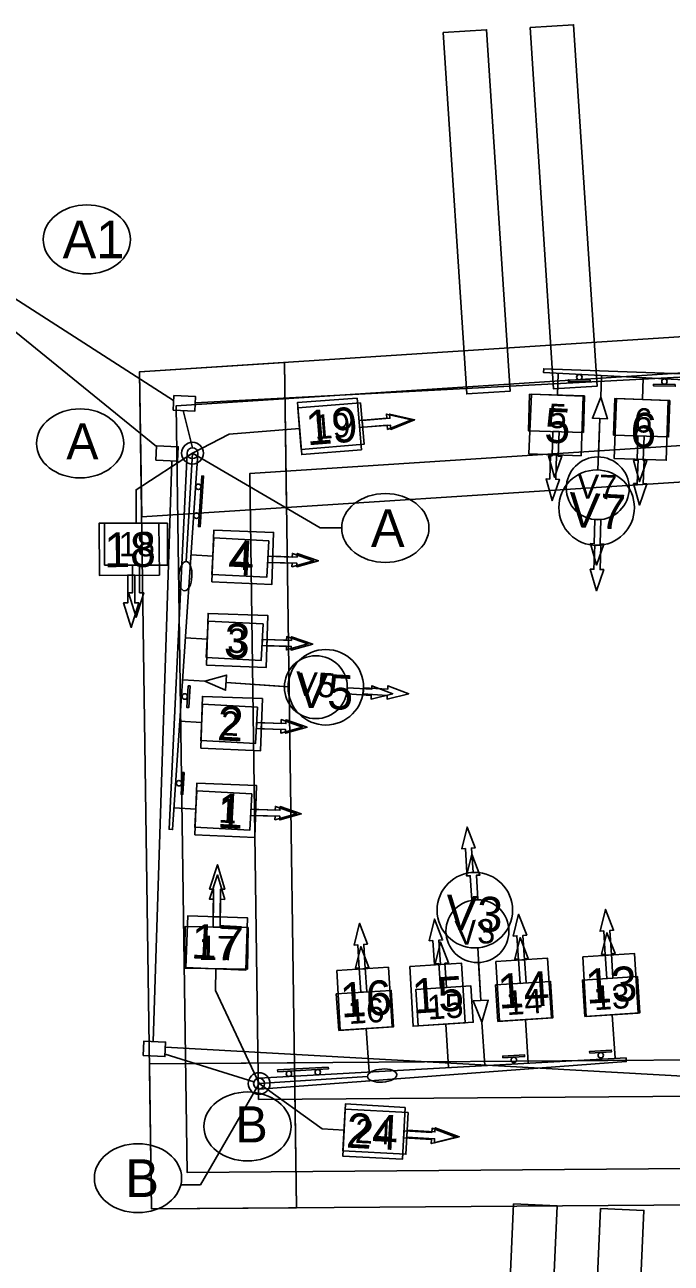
# Model space of a CAD drawing. Extents: x 21 to 686546, y 24 to 735466.
# Drawn here: x 686181.5 to 686270.7, y 734785.5 to 734956.5 of the extents above; entities that cross this region are included whole.
import ezdxf

# ---------------------------------------------------------------- set-up
doc = ezdxf.new("R2010")
doc.units = 0
for name, color, linetype in [('PEDXLIMITS-PR', 7, 'Continuous'), ('signal wiring diagram', 7, 'Continuous'), ('SIGNAL-PLAN VIEW LABLES', 7, 'Continuous'), ('SIGNAL-PR', 7, 'Continuous'), ('signal-pr-conduit', 7, 'Continuous'), ('Video-Zones-pr', 7, 'Continuous')]:
    doc.layers.add(name, color=color, linetype=linetype)

# ---------------------------------------------------------------- blocks, each defined once
blk = doc.blocks.new('R10-12 SIGN')
at = {"layer": 'SIGNAL-PR'}
blk.add_lwpolyline([(1.52, 0.75), (-1.48, 0.75), (-1.48, 1), (1.52, 1), (1.52, 0.75)], close=True, dxfattribs=at)
blk.add_circle((0.02, 0.37), 0.375, dxfattribs=at)
blk = doc.blocks.new('STREET NAME SIGN')
at = {"layer": 'SIGNAL-PR'}
blk.add_lwpolyline([(1.5, 0.96), (1.49, 0.71), (-5.5, 0.9), (-5.5, 1.15)], close=True, dxfattribs=at)
for centre in [(-4, 0.49), (-0.01, 0.37)]:
    blk.add_circle(centre, 0.375, dxfattribs=at)

msp = doc.modelspace()

# ---------------------------------------------------------------- linework, layer by layer
at = {"layer": 'PEDXLIMITS-PR'}
for p, q in [((686197.36, 734908.57), (686325.63, 734916.9)), ((686218.99, 734793.17), (686217.35, 734909.86)), ((686198.99, 734793.02), (686197.36, 734908.57)), ((686197.65, 734888.54), (686324.47, 734896.78)), ((686319.7, 734813.93), (686198.71, 734813.02)), ((686318.55, 734793.92), (686198.99, 734793.02))]:
    msp.add_line(p, q, dxfattribs=at)
for points in [[(686320.31, 734911.54), (686313.83, 734798.89), (686203.92, 734798.05), (686202.43, 734903.89)], [(686217.63, 734889.84), (686197.65, 734888.54), (686197.36, 734908.57), (686217.35, 734909.86)], [(686304.38, 734808.81), (686213.78, 734808.13), (686212.56, 734894.52), (686309.68, 734900.83)], [(686218.99, 734793.17), (686198.99, 734793.02), (686198.71, 734813.02), (686218.71, 734813.17)]]:
    msp.add_lwpolyline(points, close=True, dxfattribs=at)
at = {"layer": 'signal wiring diagram'}
for p in [(686207.84, 734823.15), (686222.57, 734804.06)]:
    msp.add_line(p, (686213.84, 734810.31), dxfattribs=at)
for points in [[(686255.09, 734908.35), (686254.99, 734905.36)], [(686261.08, 734908.05), (686260.97, 734905.08)], [(686266.82, 734907.75), (686266.73, 734904.75)], [(686231.97, 734901.21), (686232.02, 734900.63), (686235.3, 734901.95), (686231.85, 734902.74), (686231.9, 734902.16), (686228.07, 734901.87), (686228.14, 734900.91), (686231.97, 734901.21)], [(686228.14, 734900.91), (686231.97, 734901.21), (686232.02, 734900.63), (686235.3, 734901.95), (686231.85, 734902.74), (686231.9, 734902.16), (686228.07, 734901.87)], [(686260.86, 734902.12), (686260.66, 734896.84)], [(686204.66, 734897.34), (686209.73, 734899.98), (686219.43, 734900.73)], [(686254.27, 734896.97), (686253.77, 734896.99), (686254.6, 734894.01), (686255.62, 734896.93), (686255.11, 734896.95), (686255.22, 734900.31), (686254.38, 734900.33), (686254.27, 734896.97)], [(686254.38, 734900.33), (686254.27, 734896.97), (686253.77, 734896.99), (686254.6, 734894.01), (686255.62, 734896.93), (686255.11, 734896.95), (686255.22, 734900.31)], [(686266.01, 734896.37), (686265.5, 734896.39), (686266.34, 734893.41), (686267.35, 734896.33), (686266.85, 734896.34), (686266.95, 734899.7), (686266.11, 734899.73), (686266.01, 734896.37)], [(686266.11, 734899.73), (686266.01, 734896.37), (686265.5, 734896.39), (686266.34, 734893.41), (686267.35, 734896.33), (686266.85, 734896.34), (686266.95, 734899.7)], [(686204.66, 734897.34), (686196.87, 734892.28), (686196.88, 734887.66)], [(686260.05, 734884.84), (686259.55, 734884.85), (686260.38, 734881.88), (686261.39, 734884.8), (686260.89, 734884.81), (686261, 734888.17), (686260.16, 734888.2), (686260.05, 734884.84)], [(686260.16, 734888.2), (686260.05, 734884.84), (686259.55, 734884.85), (686260.38, 734881.88), (686261.39, 734884.8), (686260.89, 734884.81), (686261, 734888.17)], [(686204.47, 734883.3), (686207.46, 734883.13)], [(686218.4, 734882.15), (686218.38, 734881.65), (686221.36, 734882.48), (686218.44, 734883.5), (686218.43, 734882.99), (686215.07, 734883.1), (686215.04, 734882.26), (686218.4, 734882.15)], [(686215.04, 734882.26), (686218.4, 734882.15), (686218.38, 734881.65), (686221.36, 734882.48), (686218.44, 734883.5), (686218.43, 734882.99), (686215.07, 734883.1)], [(686196.4, 734878.06), (686195.82, 734878.06), (686196.88, 734874.69), (686197.94, 734878.06), (686197.36, 734878.06), (686197.36, 734881.9), (686196.4, 734881.9), (686196.4, 734878.06)], [(686196.4, 734881.9), (686196.4, 734878.06), (686195.82, 734878.06), (686196.88, 734874.69), (686197.94, 734878.06), (686197.36, 734878.06), (686197.36, 734881.9)], [(686203.7, 734871.83), (686206.69, 734871.65)], [(686217.63, 734870.68), (686217.61, 734870.18), (686220.59, 734871.01), (686217.67, 734872.02), (686217.65, 734871.52), (686214.3, 734871.62), (686214.27, 734870.79), (686217.63, 734870.68)], [(686214.27, 734870.79), (686217.63, 734870.68), (686217.61, 734870.18), (686220.59, 734871.01), (686217.67, 734872.02), (686217.65, 734871.52), (686214.3, 734871.62)], [(686203.31, 734866.06), (686206.34, 734865.86)], [(686209.29, 734865.66), (686217.34, 734865.12)], [(686229.32, 734863.9), (686229.29, 734863.4), (686232.29, 734864.12), (686229.41, 734865.24), (686229.38, 734864.74), (686226.03, 734864.96), (686225.97, 734864.12), (686229.32, 734863.9)], [(686225.97, 734864.12), (686229.32, 734863.9), (686229.29, 734863.4), (686232.29, 734864.12), (686229.41, 734865.24), (686229.38, 734864.74), (686226.03, 734864.96)], [(686202.92, 734860.35), (686205.92, 734860.18)], [(686216.86, 734859.2), (686216.84, 734858.7), (686219.82, 734859.53), (686216.9, 734860.55), (686216.88, 734860.04), (686213.52, 734860.15), (686213.5, 734859.31), (686216.86, 734859.2)], [(686213.5, 734859.31), (686216.86, 734859.2), (686216.84, 734858.7), (686219.82, 734859.53), (686216.9, 734860.55), (686216.88, 734860.04), (686213.52, 734860.15)], [(686202.12, 734848.38), (686205.12, 734848.21)], [(686216.05, 734847.23), (686216.04, 734846.73), (686219.01, 734847.56), (686216.09, 734848.57), (686216.08, 734848.07), (686212.72, 734848.18), (686212.69, 734847.34), (686216.05, 734847.23)], [(686212.69, 734847.34), (686216.05, 734847.23), (686216.04, 734846.73), (686219.01, 734847.56), (686216.09, 734848.57), (686216.08, 734848.07), (686212.72, 734848.18)], [(686243.82, 734839.06), (686244.32, 734839.09), (686243.21, 734841.98), (686242.48, 734838.97), (686242.98, 734839.01), (686243.2, 734835.65), (686244.04, 734835.71), (686243.82, 734839.06)], [(686244.04, 734835.71), (686243.82, 734839.06), (686244.32, 734839.09), (686243.21, 734841.98), (686242.48, 734838.97), (686242.98, 734839.01), (686243.2, 734835.65)], [(686208.52, 734835.75), (686209.1, 734835.74), (686208.09, 734839.12), (686206.99, 734835.77), (686207.56, 734835.76), (686207.5, 734831.92), (686208.46, 734831.91), (686208.52, 734835.75)], [(686208.46, 734831.91), (686208.52, 734835.75), (686209.1, 734835.74), (686208.09, 734839.12), (686206.99, 734835.77), (686207.56, 734835.76), (686207.5, 734831.92)], [(686250.46, 734827.55), (686250.96, 734827.58), (686249.85, 734830.47), (686249.12, 734827.47), (686249.62, 734827.5), (686249.84, 734824.14), (686250.68, 734824.2), (686250.46, 734827.55)], [(686250.68, 734824.2), (686250.46, 734827.55), (686250.96, 734827.58), (686249.85, 734830.47), (686249.12, 734827.47), (686249.62, 734827.5), (686249.84, 734824.14)], [(686262.44, 734828.23), (686262.95, 734828.26), (686261.83, 734831.14), (686261.1, 734828.14), (686261.6, 734828.17), (686261.82, 734824.82), (686262.66, 734824.87), (686262.44, 734828.23)], [(686262.66, 734824.87), (686262.44, 734828.23), (686262.95, 734828.26), (686261.83, 734831.14), (686261.1, 734828.14), (686261.6, 734828.17), (686261.82, 734824.82)], [(686228.49, 734826.31), (686229, 734826.35), (686227.88, 734829.23), (686227.15, 734826.23), (686227.66, 734826.26), (686227.87, 734822.91), (686228.71, 734822.96), (686228.49, 734826.31)], [(686228.71, 734822.96), (686228.49, 734826.31), (686229, 734826.35), (686227.88, 734829.23), (686227.15, 734826.23), (686227.66, 734826.26), (686227.87, 734822.91)], [(686239.48, 734826.93), (686239.98, 734826.97), (686238.87, 734829.85), (686238.14, 734826.85), (686238.64, 734826.88), (686238.86, 734823.53), (686239.7, 734823.58), (686239.48, 734826.93)], [(686239.7, 734823.58), (686239.48, 734826.93), (686239.98, 734826.97), (686238.87, 734829.85), (686238.14, 734826.85), (686238.64, 734826.88), (686238.86, 734823.53)], [(686244.43, 734821.77), (686244.13, 734827.01)], [(686207.84, 734823.15), (686207.89, 734826.15)], [(686262.96, 734813.83), (686262.57, 734819.82)], [(686239.99, 734812.54), (686239.6, 734818.52)], [(686244.98, 734812.82), (686244.59, 734818.81)], [(686250.97, 734813.16), (686250.59, 734819.14)], [(686229.01, 734811.92), (686228.62, 734817.9)], [(686222.57, 734804.06), (686225.57, 734803.89)], [(686238.06, 734802.69), (686238.03, 734802.11), (686241.45, 734802.97), (686238.15, 734804.22), (686238.11, 734803.64), (686234.28, 734803.86), (686234.23, 734802.9), (686238.06, 734802.69)], [(686234.23, 734802.9), (686238.06, 734802.69), (686238.03, 734802.11), (686241.45, 734802.97), (686238.15, 734804.22), (686238.11, 734803.64), (686234.28, 734803.86)]]:
    msp.add_lwpolyline(points, dxfattribs=at)
for points in [[(686258.75, 734905.24), (686258.59, 734900.2), (686251, 734900.44), (686251.16, 734905.48)], [(686227.85, 734904.31), (686228.32, 734898.57), (686219.67, 734897.86), (686219.2, 734903.6)], [(686260.97, 734905.08), (686261.9, 734902.08), (686259.82, 734902.17)], [(686270.49, 734904.63), (686270.33, 734899.59), (686262.74, 734899.84), (686262.9, 734904.87)], [(686201.22, 734887.66), (686201.22, 734881.9), (686192.54, 734881.9), (686192.54, 734887.66)], [(686215.18, 734885.24), (686214.91, 734880.21), (686207.33, 734880.61), (686207.6, 734885.64)], [(686214.41, 734873.77), (686214.14, 734868.73), (686206.56, 734869.14), (686206.82, 734874.17)], [(686206.34, 734865.86), (686209.37, 734866.7), (686209.22, 734864.62)], [(686213.64, 734862.29), (686213.37, 734857.26), (686205.79, 734857.66), (686206.05, 734862.7)], [(686212.83, 734850.32), (686212.57, 734845.29), (686204.98, 734845.69), (686205.25, 734850.72)], [(686212.32, 734831.85), (686212.23, 734826.09), (686203.55, 734826.22), (686203.64, 734831.98)], [(686258.78, 734819.57), (686258.45, 734824.6), (686266.03, 734825.09), (686266.36, 734820.06)], [(686224.83, 734817.66), (686224.5, 734822.69), (686232.08, 734823.18), (686232.41, 734818.15)], [(686235.81, 734818.28), (686235.49, 734823.31), (686243.07, 734823.8), (686243.39, 734818.77)], [(686246.8, 734818.9), (686246.47, 734823.93), (686254.05, 734824.42), (686254.38, 734819.39)], [(686244.59, 734818.81), (686243.39, 734821.72), (686245.47, 734821.82)], [(686234.39, 734806.32), (686234.09, 734800.56), (686225.42, 734801.02), (686225.72, 734806.77)]]:
    msp.add_lwpolyline(points, close=True, dxfattribs=at)
for centre in [(686260.56, 734892.49), (686221.68, 734865.03), (686243.97, 734831.35)]:
    msp.add_circle(centre, 4.34, dxfattribs=at)
for centre in [(686189.16, 734898.69), (686212.25, 734804.39)]:
    msp.add_ellipse(centre, major_axis=(-6.02, 0), ratio=0.790685, dxfattribs=at)
at = {"layer": 'SIGNAL-PLAN VIEW LABLES'}
for p in [(686207.84, 734823.15), (686222.57, 734804.06)]:
    msp.add_line(p, (686213.84, 734810.31), dxfattribs=at)
for points in [[(686255.09, 734908.35), (686254.99, 734905.36)], [(686261.08, 734908.05), (686260.97, 734905.08)], [(686266.82, 734907.75), (686266.73, 734904.75)], [(686231.53, 734901.2), (686231.58, 734900.63), (686234.86, 734901.94), (686231.42, 734902.73), (686231.46, 734902.16), (686227.63, 734901.86), (686227.71, 734900.9), (686231.53, 734901.2)], [(686227.71, 734900.9), (686231.53, 734901.2), (686231.58, 734900.63), (686234.86, 734901.94), (686231.42, 734902.73), (686231.46, 734902.16), (686227.63, 734901.86)], [(686260.86, 734902.12), (686260.59, 734895.03)], [(686204.66, 734897.34), (686209.73, 734899.98), (686219.43, 734900.73)], [(686204.66, 734897.34), (686196.87, 734892.28), (686196.88, 734887.66)], [(686204.66, 734897.34), (686222.27, 734887.02), (686225.25, 734887.02)], [(686253.94, 734893.76), (686253.43, 734893.78), (686254.26, 734890.8), (686255.28, 734893.72), (686254.77, 734893.74), (686254.88, 734897.09), (686254.04, 734897.12), (686253.94, 734893.76)], [(686254.04, 734897.12), (686253.94, 734893.76), (686253.43, 734893.78), (686254.26, 734890.8), (686255.28, 734893.72), (686254.77, 734893.74), (686254.88, 734897.09)], [(686266.01, 734893.15), (686265.51, 734893.16), (686266.34, 734890.18), (686267.35, 734893.1), (686266.85, 734893.12), (686266.96, 734896.48), (686266.12, 734896.5), (686266.01, 734893.15)], [(686266.12, 734896.5), (686266.01, 734893.15), (686265.51, 734893.16), (686266.34, 734890.18), (686267.35, 734893.1), (686266.85, 734893.12), (686266.96, 734896.48)], [(686260.04, 734881.31), (686259.54, 734881.32), (686260.37, 734878.34), (686261.39, 734881.26), (686260.88, 734881.28), (686260.99, 734884.64), (686260.15, 734884.66), (686260.04, 734881.31)], [(686260.15, 734884.66), (686260.04, 734881.31), (686259.54, 734881.32), (686260.37, 734878.34), (686261.39, 734881.26), (686260.88, 734881.28), (686260.99, 734884.64)], [(686204.47, 734883.3), (686207.46, 734883.13)], [(686219.06, 734882.15), (686219.04, 734881.65), (686222.02, 734882.48), (686219.1, 734883.5), (686219.08, 734882.99), (686215.72, 734883.1), (686215.7, 734882.26), (686219.06, 734882.15)], [(686215.7, 734882.26), (686219.06, 734882.15), (686219.04, 734881.65), (686222.02, 734882.48), (686219.1, 734883.5), (686219.08, 734882.99), (686215.72, 734883.1)], [(686195.73, 734876.66), (686195.15, 734876.66), (686196.21, 734873.29), (686197.26, 734876.66), (686196.69, 734876.66), (686196.69, 734880.5), (686195.73, 734880.5), (686195.73, 734876.66)], [(686195.73, 734880.5), (686195.73, 734876.66), (686195.15, 734876.66), (686196.21, 734873.29), (686197.26, 734876.66), (686196.69, 734876.66), (686196.69, 734880.5)], [(686203.7, 734871.83), (686206.69, 734871.65)], [(686218.28, 734870.66), (686218.27, 734870.15), (686221.24, 734870.98), (686218.33, 734872), (686218.31, 734871.5), (686214.95, 734871.6), (686214.93, 734870.76), (686218.28, 734870.66)], [(686214.93, 734870.76), (686218.28, 734870.66), (686218.27, 734870.15), (686221.24, 734870.98), (686218.33, 734872), (686218.31, 734871.5), (686214.95, 734871.6)], [(686203.31, 734866.06), (686206.34, 734865.86)], [(686209.29, 734865.66), (686217.83, 734865.08)], [(686231.53, 734863.9), (686231.5, 734863.4), (686234.5, 734864.12), (686231.62, 734865.24), (686231.59, 734864.74), (686228.24, 734864.96), (686228.18, 734864.12), (686231.53, 734863.9)], [(686228.18, 734864.12), (686231.53, 734863.9), (686231.5, 734863.4), (686234.5, 734864.12), (686231.62, 734865.24), (686231.59, 734864.74), (686228.24, 734864.96)], [(686202.92, 734860.35), (686205.92, 734860.18)], [(686217.51, 734859.18), (686217.5, 734858.68), (686220.47, 734859.51), (686217.56, 734860.53), (686217.54, 734860.02), (686214.18, 734860.13), (686214.15, 734859.29), (686217.51, 734859.18)], [(686214.15, 734859.29), (686217.51, 734859.18), (686217.5, 734858.68), (686220.47, 734859.51), (686217.56, 734860.53), (686217.54, 734860.02), (686214.18, 734860.13)], [(686202.12, 734848.38), (686205.12, 734848.21)], [(686216.71, 734847.21), (686216.69, 734846.71), (686219.67, 734847.54), (686216.75, 734848.55), (686216.73, 734848.05), (686213.38, 734848.16), (686213.35, 734847.32), (686216.71, 734847.21)], [(686213.35, 734847.32), (686216.71, 734847.21), (686216.69, 734846.71), (686219.67, 734847.54), (686216.75, 734848.55), (686216.73, 734848.05), (686213.38, 734848.16)], [(686243.14, 734842.81), (686243.64, 734842.84), (686242.53, 734845.72), (686241.8, 734842.72), (686242.3, 734842.75), (686242.52, 734839.4), (686243.36, 734839.45), (686243.14, 734842.81)], [(686243.36, 734839.45), (686243.14, 734842.81), (686243.64, 734842.84), (686242.53, 734845.72), (686241.8, 734842.72), (686242.3, 734842.75), (686242.52, 734839.4)], [(686208.54, 734837.15), (686209.12, 734837.14), (686208.12, 734840.53), (686207.01, 734837.17), (686207.58, 734837.16), (686207.52, 734833.32), (686208.48, 734833.31), (686208.54, 734837.15)], [(686208.48, 734833.31), (686208.54, 734837.15), (686209.12, 734837.14), (686208.12, 734840.53), (686207.01, 734837.17), (686207.58, 734837.16), (686207.52, 734833.32)], [(686250.25, 734830.77), (686250.76, 734830.8), (686249.64, 734833.68), (686248.91, 734830.68), (686249.41, 734830.71), (686249.63, 734827.36), (686250.47, 734827.41), (686250.25, 734830.77)], [(686250.47, 734827.41), (686250.25, 734830.77), (686250.76, 734830.8), (686249.64, 734833.68), (686248.91, 734830.68), (686249.41, 734830.71), (686249.63, 734827.36)], [(686262.23, 734831.44), (686262.74, 734831.47), (686261.62, 734834.36), (686260.89, 734831.35), (686261.4, 734831.39), (686261.61, 734828.03), (686262.45, 734828.09), (686262.23, 734831.44)], [(686262.45, 734828.09), (686262.23, 734831.44), (686262.74, 734831.47), (686261.62, 734834.36), (686260.89, 734831.35), (686261.4, 734831.39), (686261.61, 734828.03)], [(686228.29, 734829.53), (686228.79, 734829.56), (686227.68, 734832.44), (686226.95, 734829.44), (686227.45, 734829.47), (686227.67, 734826.12), (686228.5, 734826.17), (686228.29, 734829.53)], [(686228.5, 734826.17), (686228.29, 734829.53), (686228.79, 734829.56), (686227.68, 734832.44), (686226.95, 734829.44), (686227.45, 734829.47), (686227.67, 734826.12)], [(686238.65, 734830.11), (686239.15, 734830.14), (686238.04, 734833.02), (686237.31, 734830.02), (686237.81, 734830.05), (686238.03, 734826.7), (686238.87, 734826.75), (686238.65, 734830.11)], [(686238.87, 734826.75), (686238.65, 734830.11), (686239.15, 734830.14), (686238.04, 734833.02), (686237.31, 734830.02), (686237.81, 734830.05), (686238.03, 734826.7)], [(686244.43, 734821.77), (686244.01, 734829.03)], [(686207.84, 734823.15), (686207.89, 734826.15)], [(686262.96, 734813.83), (686262.57, 734819.82)], [(686239.99, 734812.54), (686239.6, 734818.52)], [(686244.98, 734812.82), (686244.59, 734818.81)], [(686250.97, 734813.16), (686250.59, 734819.14)], [(686229.01, 734811.92), (686228.62, 734817.9)], [(686213.84, 734810.31), (686205.75, 734796.33), (686203.04, 734796.33)], [(686222.57, 734804.06), (686225.57, 734803.89)], [(686237.62, 734802.61), (686237.59, 734802.03), (686241.01, 734802.9), (686237.7, 734804.14), (686237.67, 734803.57), (686233.84, 734803.79), (686233.78, 734802.83), (686237.62, 734802.61)], [(686233.78, 734802.83), (686237.62, 734802.61), (686237.59, 734802.03), (686241.01, 734802.9), (686237.7, 734804.14), (686237.67, 734803.57), (686233.84, 734803.79)]]:
    msp.add_lwpolyline(points, dxfattribs=at)
for points in [[(686251.43, 734905.48), (686258.56, 734905.23), (686258.27, 734896.98), (686251.07, 734897.23)], [(686227.37, 734904.93), (686227.96, 734897.82), (686219.73, 734897.14), (686219.14, 734904.32)], [(686260.97, 734905.08), (686261.9, 734902.08), (686259.82, 734902.17)], [(686263.16, 734904.87), (686270.3, 734904.63), (686270.01, 734896.37), (686262.81, 734896.62)], [(686200.03, 734887.66), (686200.09, 734880.52), (686191.83, 734880.46), (686191.77, 734887.66)], [(686207.34, 734879.56), (686207.59, 734886.69), (686215.84, 734886.41), (686215.59, 734879.21)], [(686206.57, 734868.09), (686206.81, 734875.22), (686215.07, 734874.93), (686214.82, 734867.73)], [(686206.34, 734865.86), (686209.37, 734866.7), (686209.22, 734864.62)], [(686205.8, 734856.61), (686206.04, 734863.75), (686214.3, 734863.46), (686214.05, 734856.26)], [(686204.99, 734844.64), (686205.24, 734851.77), (686213.49, 734851.48), (686213.24, 734844.28)], [(686203.76, 734826.33), (686204.01, 734833.46), (686212.27, 734833.18), (686212.02, 734825.98)], [(686258.51, 734827.83), (686265.63, 734828.29), (686266.16, 734820.05), (686258.97, 734819.59)], [(686234.63, 734826.48), (686241.75, 734826.94), (686242.29, 734818.7), (686235.1, 734818.23)], [(686246.52, 734827.16), (686253.65, 734827.62), (686254.18, 734819.38), (686246.99, 734818.91)], [(686224.56, 734825.92), (686231.68, 734826.38), (686232.21, 734818.14), (686225.03, 734817.67)], [(686244.59, 734818.81), (686243.39, 734821.72), (686245.47, 734821.82)], [(686234, 734806.99), (686233.63, 734799.87), (686225.38, 734800.3), (686225.76, 734807.49)]]:
    msp.add_lwpolyline(points, close=True, dxfattribs=at)
for centre in [(686260.41, 734889.82), (686223.05, 734865.02), (686243.61, 734834.25)]:
    msp.add_circle(centre, 5.21, dxfattribs=at)
for centre in [(686190.09, 734926.85), (686231.26, 734887.01), (686197.14, 734797.25)]:
    msp.add_ellipse(centre, major_axis=(-6.02, 0), ratio=0.790685, dxfattribs=at)
at = {"layer": 'SIGNAL-PR'}
for p, q in [((686204.66, 734897.34), (686203.8, 734882.37)), ((686213.84, 734810.31), (686228.81, 734811.28))]:
    msp.add_line(p, q, dxfattribs=at)
for points in [[(686315.71, 734906.73), (686253.11, 734908.99), (686253.09, 734908.46), (686315.64, 734905.23)], [(686203.91, 734897.38), (686201.42, 734845.41), (686201.92, 734845.38), (686205.41, 734897.29)], [(686213.8, 734811.06), (686264.47, 734813.86), (686264.5, 734813.34), (686213.89, 734809.56)]]:
    msp.add_lwpolyline(points, dxfattribs=at)
for points in [[(686202, 734903.3), (686205, 734903.16), (686205.09, 734905.16), (686202.1, 734905.3)], [(686199.6, 734896.36), (686202.6, 734896.22), (686202.69, 734898.22), (686199.7, 734898.35)], [(686197.86, 734814.17), (686200.86, 734814.03), (686200.95, 734816.03), (686197.95, 734816.17)]]:
    msp.add_lwpolyline(points, close=True, dxfattribs=at)
for centre, radius in [((686204.66, 734897.34), 1.5), ((686204.66, 734897.34), 0.75), ((686213.84, 734810.31), 1.5), ((686213.84, 734810.31), 0.75)]:
    msp.add_circle(centre, radius, dxfattribs=at)
for centre, major_axis in [((686203.68, 734880.35), (0.12, 2.02)), ((686230.83, 734811.41), (-2.02, -0.13))]:
    msp.add_ellipse(centre, major_axis=major_axis, ratio=0.447722, dxfattribs=at)
at = {"layer": 'signal-pr-conduit'}
for points in [[(686202.06, 734904.63), (686179.37, 734919.22)], [(686199.69, 734898.26), (686177.31, 734916.42)], [(686205.05, 734904.27), (686313.6, 734910.02)], [(686203.38, 734903.24), (686204.65, 734898.09)], [(686199.25, 734816.11), (686201.79, 734896.26)], [(686200.92, 734815.35), (686294.48, 734810.11)], [(686200.87, 734814.38), (686213.13, 734810.56)]]:
    msp.add_lwpolyline(points, dxfattribs=at)
at = {"layer": 'Video-Zones-pr'}
for points in [[(686251.24, 734956.1), (686254.48, 734906.2), (686260.47, 734906.59), (686257.23, 734956.48)], [(686239.26, 734955.41), (686242.5, 734905.52), (686248.49, 734905.91), (686245.24, 734955.8)], [(686248.95, 734793.69), (686246.74, 734743.74), (686252.73, 734743.48), (686254.95, 734793.43)], [(686260.94, 734793.07), (686258.72, 734743.11), (686264.72, 734742.85), (686266.93, 734792.8)]]:
    msp.add_lwpolyline(points, close=True, dxfattribs=at)

# ---------------------------------------------------------------- block references
at = {"layer": 'SIGNAL-PR'}
for p, yscale, rotation in [((686258.01, 734908.2), -0.9999999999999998, -0.6626131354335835), ((686269.75, 734907.6), -1, -0.5657933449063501), ((686203.23, 734863.75), -1, 86.5372442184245), ((686202.42, 734851.78), -1, 86.5372442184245), ((686261.02, 734813.85), -1, -176.5248715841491), ((686249.03, 734813.19), -1, -176.5248715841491)]:
    msp.add_blockref('R10-12 SIGN', p, dxfattribs=dict(at, yscale=yscale, rotation=rotation))
for p, rotation in [((686204.83, 734888.72), -92.2398247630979), ((686221.98, 734811.51), 4.773311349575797)]:
    msp.add_blockref('STREET NAME SIGN', p, dxfattribs=dict(at, rotation=rotation))

# ---------------------------------------------------------------- texts
at = {"layer": 'signal wiring diagram'}
for s, rotation, p in [('5', 358.1697, (686253.73, 734900.83)), ('6', 358.1697, (686265.54, 734900.23)), ('19', 4.6785, (686221.58, 734899.23)), ('V7', 358.1697, (686257.68, 734891.12)), ('18', 0.0037, (686194.48, 734883.1)), ('4', 356.9474, (686210.05, 734881.31)), ('3', 356.9474, (686209.43, 734869.83)), ('V5', 356.9474, (686218.8, 734863.87)), ('2', 356.9474, (686208.51, 734858.41)), ('1', 356.9474, (686208.2, 734846.36)), ('V3', 3.6963, (686241, 734829.38)), ('17', 359.0877, (686205.51, 734827.39)), ('14', 3.6963, (686248.03, 734819.75)), ('13', 3.6963, (686260.09, 734820.43)), ('16', 3.6963, (686226.23, 734818.52)), ('15', 3.6963, (686237.13, 734819.13)), ('24', 356.9947, (686227.02, 734802.14))]:
    msp.add_text(s, height=3.36, rotation=rotation, dxfattribs=at).set_placement(p)
for s, p in [('A', (686187.25, 734896.47)), ('B', (686210.59, 734802.18))]:
    msp.add_text(s, height=4.99, dxfattribs=at).set_placement(p)
at = {"layer": 'SIGNAL-PLAN VIEW LABLES'}
for s, p in [('A1', (686186.75, 734924.25)), ('A', (686229.28, 734884.41)), ('B', (686195.4, 734794.65))]:
    msp.add_text(s, height=5.2, dxfattribs=at).set_placement(p)
for s, rotation, p in [('19', 4.6785, (686220.48, 734898.41)), ('5', 357.0414, (686253.12, 734898.83)), ('6', 357.0414, (686264.97, 734898.22)), ('V7', 357.0414, (686256.45, 734887.18)), ('18', 0.4523, (686192.49, 734881.59)), ('4', 357.0414, (686209.5, 734880.61)), ('3', 357.0414, (686208.92, 734869.13)), ('V5', 357.0414, (686218.89, 734862.27)), ('2', 357.0414, (686208, 734857.72)), ('1', 357.0414, (686208, 734845.65)), ('V3', 357.0414, (686239.49, 734831.61)), ('17', 357.0414, (686204.39, 734827.61)), ('13', 3.6963, (686259.01, 734821.32)), ('15', 3.6963, (686235.09, 734819.96)), ('14', 3.6963, (686246.91, 734820.63)), ('16', 3.6963, (686225.17, 734819.41)), ('24', 357.0414, (686225.78, 734801.48))]:
    msp.add_text(s, height=4.8, rotation=rotation, dxfattribs=at).set_placement(p)

doc.saveas('drawing.dxf')
